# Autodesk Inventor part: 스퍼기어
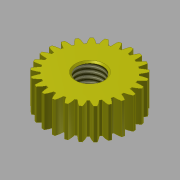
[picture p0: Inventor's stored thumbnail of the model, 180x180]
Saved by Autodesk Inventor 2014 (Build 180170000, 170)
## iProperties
Created: 2017-04
Part Number: 스퍼기어
Material: 강철
Document SubType Name: Modeling
Designer: mduedu
Categories: <?xml version="1.0" encoding="UTF-16"?> <MemberInstance><Categories><FamilyTemplate><FamilyTemplateParameter ValueType="xs:double" Id="1" ObjectReferenceKey="da
Density: 7.85 g/cm^3
Mass: 33.8546 g
Surface Area: 26.941 cm^2
Volume: 4.31269 cm^3
Appearance: 노란색
Author: mduedu
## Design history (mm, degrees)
sketch "Sketch1"
  geometry: C1 r 13.5 at (0, 0)
  constraints: 1 centre point
  dimensions: "d0" = 27 diameter of C1 (= da_da)
extrude "Extrusion1" new body sketch "Sketch1" distance "d1" = 10 (= da_b); taper "d2" = 0 deg
workplane "Work Plane2"
sketch "Sketch2"
  geometry: C1 r 13.5 at (0, 0) reference; C2 r 12.5 at (0, 0)
  constraints: 1 centre point, 1 coincident
  dimensions: "d3" = 25 diameter of C2 (= da_dw)
feature "피치 지름" sketch "Sketch2" dims "d4" = 10, "d5" = 0
workplane "Work Plane8"
workplane "Work Plane9"
feature "스퍼 기어" dims "da_b" = 10, "da_d" = 25, "da_aw" = 25, "da_da" = 27, "da_df" = 22.5, "da_dw" = 25, angle "da_beta" = 0 deg, "da_lefttooth" = 0, "da_righttooth" = 0
sketch "스케치3"
  geometry: C1 r 4.188 at (0, 0); 1 further point
  constraints: 1 centre point, 1 coincident
  dimensions: "d49" = 8.376 diameter of C1
extrude "돌출2" cut sketch "스케치3" stored distance "d50" = 10; taper "d51" = 0 deg
feature "스레드1" dims "d52" = 10, "d53" = 0
chamfer "모따기1" distance "d54" = 0.5; stored, may be unused: second distance "d55" = 2, angle "d56" = 45 deg
body "Solid1"
body "Srf1"
other parameters: "d16" = 25 (= da_aw), "d17" = 0, "d34" = 1.25664 (computed from da_z), "d39" = 0, "d41" = 0, "d43" = 25 (= da_aw), "d46" = 25 (= da_aw), "d47" = 0, "d48" = 0
